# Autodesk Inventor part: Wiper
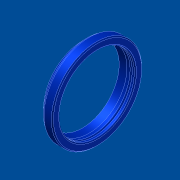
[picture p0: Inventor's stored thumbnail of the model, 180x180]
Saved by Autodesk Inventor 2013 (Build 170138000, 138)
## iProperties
Shininess: 20.0
Length Units: 11269
Angle Units: 11279
Time Units: 11290
Mass Units: 11283
Length Display Precision: 3
Angle Display Precision: 2
Created: 2001-04
Part Number: Wiper
Material: Standard
Document SubType Name: Modellieren
Designer: dl
Density: 1 g/cm^3
Density: 0.0
Volumn: 0.0
Area: 0.0
PropertySet Name: Model Information
Control State: 0
Master: False
Checked Out: False
Author: dl
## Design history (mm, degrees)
body "Solid1"
revolve "Revolution1" stored, may be unused: angle "d7" = 90 deg
revolve "Revolution2" stored, may be unused: angle "d15" = 90 deg
revolve "Revolution3" stored, may be unused: angle "d29" = 90 deg
fillet "Fillet1" dims "d30" = 0.5
chamfer "Chamfer1" distance "d31" = 0.5; stored, may be unused: second distance "d32" = 0.5, angle "d33" = 45 deg
sketch "Sketch1"
  geometry: L1 (0, 0)-(0, 18.5); L2 (0, 18.5)-(2.2, 19.5); L3 (2.2, 19.5)-(2.2, 20.8); L4 (2.2, 20.8)-(3.2, 20.8); L5 (3.2, 20.8)-(3.2, 21.5); L6 (3.2, 21.5)-(7.2, 21.5); L7 (7.2, 21.5)-(7.2, 0); L8 (7.2, 0)-(0, 0)
  constraints: 16 end point, 4 parallel, 2 vertical, 1 perpendicular
  dimensions: "d0" = 21.5 distance of L6.end L7.end; "d1" = 20.8 distance between parallel lines of L8 L4; "d2" = 19.5 distance from line of L8 L2.end; "d3" = 18.5 distance of L1.start L1.end; "d4" = 4 distance of L5.end L6.end; "d5" = 5 distance between parallel lines of L7 L3; "d6" = 7.2 distance of L7.end L1.start
sketch "Sketch2"
  geometry: L1 (0, 0)-(0, 17.5); L2 (0, 17.5)-(3.2, 18); L3 (3.2, 18)-(7.2, 18); L4 (7.2, 18)-(7.2, 0); L5 (7.2, 0)-(0, 0); L6 (0, -18.5)-(0, 18.5) reference; L7 (7.2, -21.5)-(7.2, 21.5) reference; L8 (0, 0)-(12.248, 0)
  constraints: 12 end point, 2 parallel, 2 perpendicular, 1 midpoint, 1 vertical
  dimensions: "d8" = 17.5 distance of L1.start L1.end; "d10" = 18 distance of L3.end L4.end; "d11" = 0 distance between parallel lines of L6 L1; "d12" = 0 distance between parallel lines of L4 L7; "d13" = 0 distance between parallel lines of L5 L8; "d14" = 4 distance of L2.end L3.end
sketch "Sketch3"
  geometry: L1 (-5.7, 18)-(-4.7, 18); L2 (-7.2, 21.5)-(-7.2, -21.5) reference; L3 (-7.2, 0)-(6.266, 0); A1 r 0.5 centre (-5.7, 18.5) between (-5.7, 18) and (-5.2, 18.5); A2 r 0.5 centre (-4.7, 18.5) between (-5.2, 18.5) and (-4.7, 18)
  constraints: 4 end point, 4 point on circle, 2 centre point, 1 equal radius, 1 horizontal, 1 midpoint, 1 perpendicular
  dimensions: "d22" = 0.5 radius of A2; "d23" = 0 distance edge to line of A1 L1; "d25" = 0.5 distance from line of L1 A2.centre; "d26" = 1 distance of A1.centre A2.centre; "d27" = 2 distance from line of L2 A1.end; "d28" = 36 diameter of L1 L3
